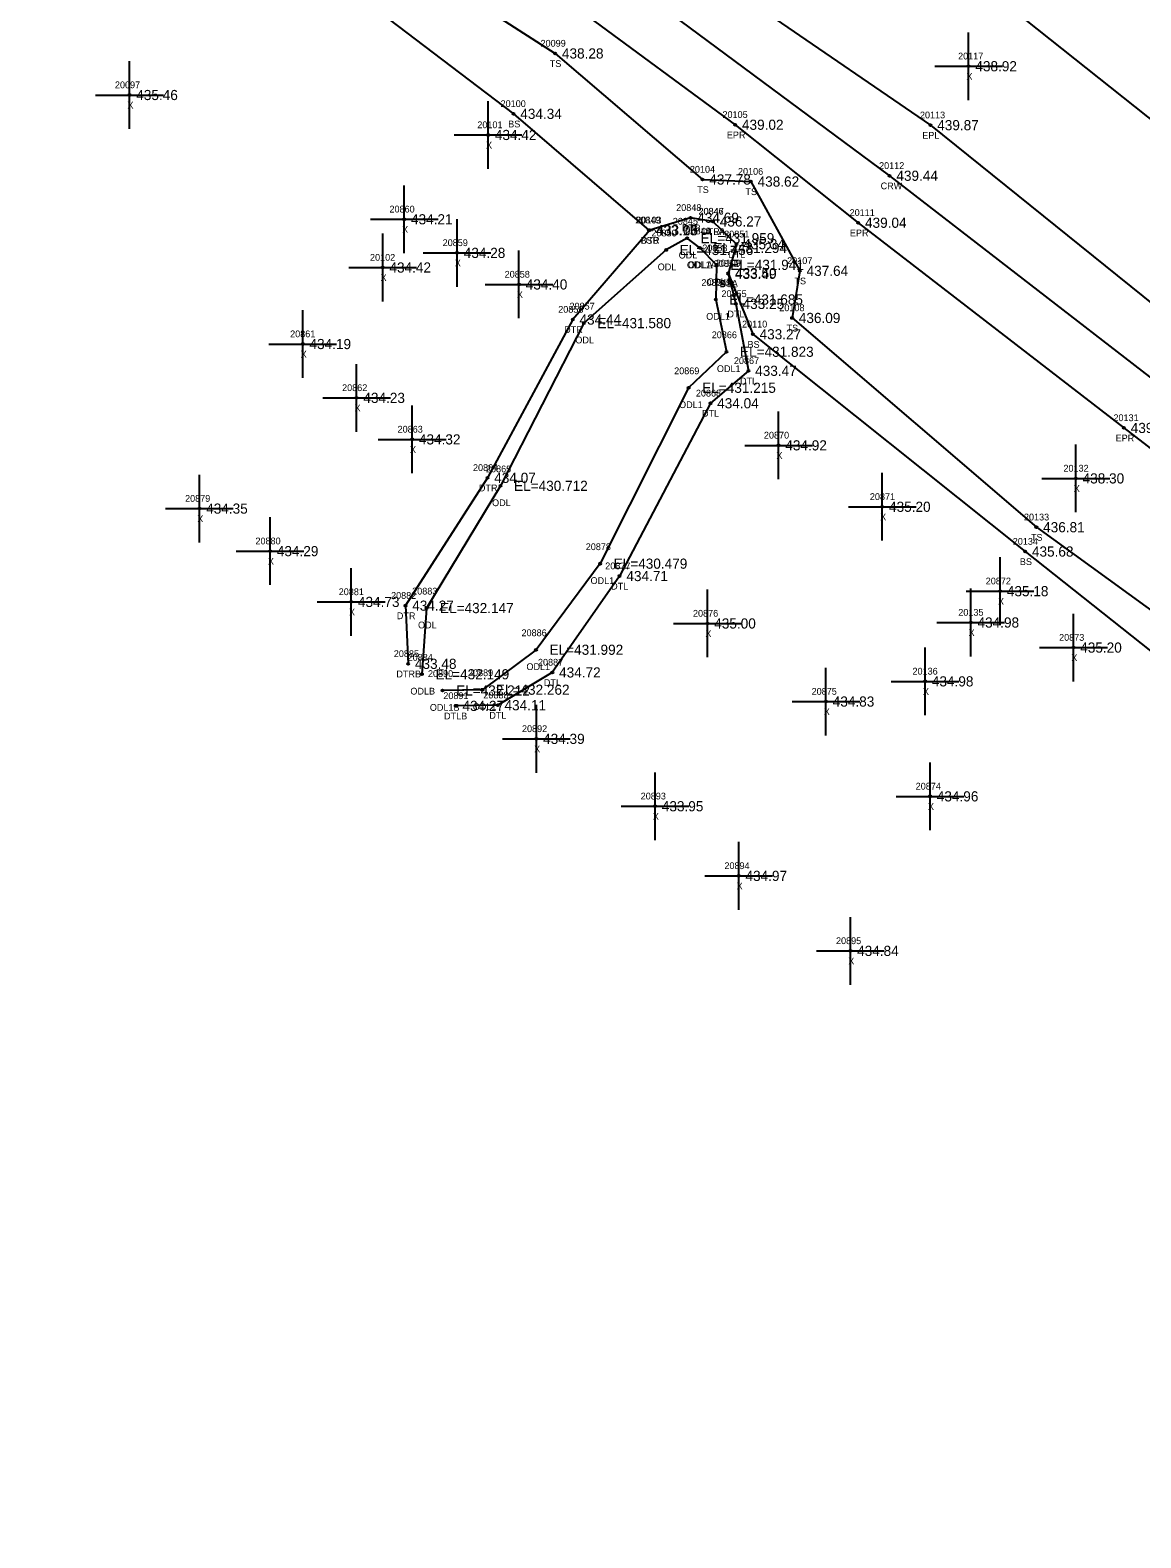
# Model space of a CAD drawing. Extents: x 1613836 to 1615109, y 777151 to 778248.
# Drawn here: x 1614083 to 1614247, y 777695.6 to 777918.3 of the extents above; entities that cross this region are included whole.
import ezdxf

# ---------------------------------------------------------------- set-up
doc = ezdxf.new("R2010")
doc.units = 0
for name, color, linetype in [('RD_DTM_BkLn1', 7, 'Continuous'), ('RD_DTM_BkLn2', 7, 'Continuous'), ('RD_DTM_BkLn_txCode', 7, 'Continuous'), ('RD_EX_H2O', 7, 'Continuous'), ('RD_EX_H2O_txCode', 7, 'Continuous'), ('RD_EX_Misc', 7, 'Continuous'), ('RD_EX_Misc_txCode', 7, 'Continuous'), ('RD_EX_Road', 7, 'Continuous'), ('RD_EX_Road_txCode', 7, 'Continuous'), ('RD_EX_TX_H2O_ELEV', 7, 'Continuous'), ('RD_EX_TX_Misc_ELEV', 7, 'Continuous'), ('RD_EX_TX_Road_ELEV', 7, 'Continuous'), ('RD_HC_Survey_ELEV', 7, 'Continuous'), ('RD_HC_Survey_txCode', 7, 'Continuous'), ('RD_SMD_Locator', 7, 'Continuous')]:
    doc.layers.add(name, color=color, linetype=linetype)

msp = doc.modelspace()

# ---------------------------------------------------------------- linework, layer by layer
at = {"layer": 'RD_DTM_BkLn1'}
msp.add_lwpolyline([(1613865.21, 778095.86), (1613910.73, 778075.92), (1613956.18, 778054.99), (1614000.73, 778032.51), (1614044.52, 778008.68), (1614087.21, 777982.81), (1614129.12, 777955.82), (1614169.63, 777926.64), (1614209.9, 777896.76), (1614249.35, 777866.21), (1614288.43, 777835.55), (1614366.39, 777772.65), (1614443.98, 777709.72)], dxfattribs=at)
at = {"layer": 'RD_DTM_BkLn2'}
for points in [[(1613870.65, 778107.91), (1613917.36, 778089.81), (1613963.47, 778068.53), (1614008.76, 778046.32), (1614052.42, 778023.01), (1614094.96, 777996.37), (1614137.71, 777969), (1614179.06, 777940.06), (1614196.49, 777927.41), (1614202.23, 777922.93), (1614210.94, 777920.91), (1614226.4, 777922.61), (1614267.62, 777889.85), (1614307.16, 777859.76), (1614381.32, 777790.21), (1614451.43, 777721.4), (1614453.49, 777722.08), (1614455.33, 777720.48), (1614437.07, 777696.16)], [(1613860.36, 778083.39), (1613904.96, 778062.9), (1613950.73, 778042.94), (1613994.86, 778021.25), (1614038.25, 777997.65), (1614118.58, 777941.84), (1614160.54, 777914.82), (1614182.29, 777896.21), (1614189.42, 777895.9), (1614196.65, 777882.72), (1614195.5, 777875.76), (1614231.56, 777844.86), (1614271.92, 777815.6), (1614305.89, 777789.49), (1614313.92, 777782.98), (1614351.2, 777751.93), (1614424.47, 777701.24), (1614433.25, 777695.63), (1614437.07, 777696.16)], [(1613858.47, 778079.63), (1613903.77, 778059.57), (1613949.1, 778039.22), (1613993.41, 778017.95), (1614036.6, 777992.42), (1614114.93, 777935.94), (1614154.39, 777905.9), (1614174.38, 777888.71)], [(1614186.09, 777882.37), (1614189.71, 777873.35), (1614229.91, 777841.27), (1614268.42, 777810.69), (1614296.8, 777785.63)]]:
    msp.add_lwpolyline(points, dxfattribs=at)
at = {"layer": 'RD_EX_H2O'}
for points in [[(1614183.83, 777890.01), (1614180.52, 777890.56), (1614174.49, 777888.72), (1614163.13, 777875.53), (1614150.55, 777852.16), (1614138.44, 777833.28), (1614138.84, 777824.69)], [(1614183.83, 777890.01), (1614187.32, 777886.65), (1614186.07, 777882.28), (1614187.2, 777877.84), (1614189.06, 777867.96), (1614183.45, 777863.16), (1614170.05, 777837.65), (1614160.12, 777823.42), (1614152.06, 777818.58), (1614145.86, 777818.48)], [(1614181.88, 777886.1), (1614180.01, 777887.54), (1614176.91, 777885.8), (1614164.77, 777875), (1614152.47, 777850.97), (1614141.54, 777832.92), (1614140.88, 777823.15)], [(1614181.88, 777886.1), (1614184.37, 777883.6), (1614184.24, 777878.49), (1614185.82, 777870.77), (1614180.24, 777865.45), (1614167.17, 777839.48), (1614157.71, 777826.77), (1614149.79, 777820.87), (1614143.92, 777820.75)]]:
    msp.add_lwpolyline(points, dxfattribs=at)
at = {"layer": 'RD_EX_Misc'}
for p, q in [((1614221.56, 777907.93), (1614221.56, 777917.93)), ((1614097.71, 777903.68), (1614097.71, 777913.68)), ((1614216.56, 777912.93), (1614226.56, 777912.93)), ((1614092.71, 777908.68), (1614102.71, 777908.68)), ((1614150.64, 777897.78), (1614150.64, 777907.78)), ((1614145.64, 777902.78), (1614155.64, 777902.78)), ((1614138.26, 777885.33), (1614138.26, 777895.33)), ((1614133.26, 777890.33), (1614143.26, 777890.33)), ((1614146.05, 777880.37), (1614146.05, 777890.37)), ((1614135.08, 777878.21), (1614135.08, 777888.21)), ((1614141.05, 777885.37), (1614151.05, 777885.37)), ((1614155.2, 777875.71), (1614155.2, 777885.71)), ((1614130.08, 777883.21), (1614140.08, 777883.21)), ((1614150.2, 777880.71), (1614160.2, 777880.71)), ((1614123.28, 777866.91), (1614123.28, 777876.91)), ((1614118.28, 777871.91), (1614128.28, 777871.91)), ((1614131.23, 777858.96), (1614131.23, 777868.96)), ((1614126.23, 777863.96), (1614136.23, 777863.96)), ((1614139.43, 777852.83), (1614139.43, 777862.83)), ((1614193.51, 777851.95), (1614193.51, 777861.95)), ((1614134.43, 777857.83), (1614144.43, 777857.83)), ((1614188.51, 777856.95), (1614198.51, 777856.95)), ((1614237.39, 777847.07), (1614237.39, 777857.07)), ((1614108.03, 777842.61), (1614108.03, 777852.61)), ((1614208.82, 777842.88), (1614208.82, 777852.88)), ((1614232.39, 777852.07), (1614242.39, 777852.07)), ((1614103.03, 777847.61), (1614113.03, 777847.61)), ((1614203.82, 777847.88), (1614213.82, 777847.88)), ((1614118.46, 777836.33), (1614118.46, 777846.33)), ((1614113.46, 777841.33), (1614123.46, 777841.33)), ((1614226.21, 777830.42), (1614226.21, 777840.42)), ((1614130.43, 777828.83), (1614130.43, 777838.83)), ((1614125.43, 777833.83), (1614135.43, 777833.83)), ((1614183.02, 777825.65), (1614183.02, 777835.65)), ((1614221.21, 777835.42), (1614231.21, 777835.42)), ((1614221.88, 777825.79), (1614221.88, 777835.79)), ((1614237.04, 777822.09), (1614237.04, 777832.09)), ((1614178.02, 777830.65), (1614188.02, 777830.65)), ((1614216.88, 777830.79), (1614226.88, 777830.79)), ((1614215.14, 777817.1), (1614215.14, 777827.1)), ((1614232.04, 777827.09), (1614242.04, 777827.09)), ((1614200.51, 777814.12), (1614200.51, 777824.12)), ((1614210.14, 777822.1), (1614220.14, 777822.1)), ((1614157.76, 777808.61), (1614157.76, 777818.61)), ((1614195.51, 777819.12), (1614205.51, 777819.12)), ((1614152.76, 777813.61), (1614162.76, 777813.61)), ((1614215.87, 777800.12), (1614215.87, 777810.12)), ((1614175.28, 777798.66), (1614175.28, 777808.66)), ((1614210.87, 777805.12), (1614220.87, 777805.12)), ((1614170.28, 777803.66), (1614180.28, 777803.66)), ((1614187.63, 777788.38), (1614187.63, 777798.38)), ((1614182.63, 777793.38), (1614192.63, 777793.38)), ((1614204.11, 777777.3), (1614204.11, 777787.3)), ((1614199.11, 777782.3), (1614209.11, 777782.3))]:
    msp.add_line(p, q, dxfattribs=at)
at = {"layer": 'RD_EX_Road'}
for points in [[(1613868.87, 778104.15), (1613915.02, 778083.82), (1613960.16, 778062.2), (1614004.58, 778040.28), (1614048.84, 778015.98), (1614091.38, 777990.08), (1614134.36, 777962.6), (1614174.73, 777933.48), (1614192.07, 777920.58), (1614215.93, 777904.23), (1614254.59, 777873.05), (1614293.82, 777842.42), (1614371.74, 777779.59), (1614449.33, 777716.3), (1614443.98, 777709.72), (1614439.38, 777704.09)], [(1613862.14, 778087.92), (1613908.12, 778068.22), (1613952.96, 778047.38), (1613997, 778025.09), (1614041.16, 778001.63), (1614124.35, 777949.06), (1614164.51, 777920.91), (1614187.11, 777904.29), (1614205.27, 777889.82), (1614244.49, 777859.52), (1614283.42, 777829.45), (1614361.06, 777765.89), (1614439.38, 777704.09)]]:
    msp.add_lwpolyline(points, dxfattribs=at)
at = {"layer": 'RD_SMD_Locator'}
for centre in [(1614160.54, 777914.82), (1614221.56, 777912.93), (1614097.71, 777908.68), (1614154.39, 777905.9), (1614150.64, 777902.78), (1614187.11, 777904.29), (1614215.93, 777904.23), (1614182.29, 777896.21), (1614189.42, 777895.9), (1614209.9, 777896.76), (1614138.26, 777890.33), (1614180.52, 777890.56), (1614183.83, 777890.01), (1614183.83, 777890.01), (1614205.27, 777889.82), (1614174.38, 777888.71), (1614174.49, 777888.72), (1614180.01, 777887.54), (1614146.05, 777885.37), (1614176.91, 777885.8), (1614181.88, 777886.1), (1614181.88, 777886.1), (1614187.32, 777886.65), (1614135.08, 777883.21), (1614184.37, 777883.6), (1614196.65, 777882.72), (1614155.2, 777880.71), (1614186.07, 777882.28), (1614186.09, 777882.37), (1614184.24, 777878.49), (1614187.2, 777877.84), (1614163.13, 777875.53), (1614164.77, 777875), (1614195.5, 777875.76), (1614123.28, 777871.91), (1614189.71, 777873.35), (1614185.82, 777870.77), (1614189.06, 777867.96), (1614180.24, 777865.45), (1614131.23, 777863.96), (1614183.45, 777863.16), (1614244.49, 777859.52), (1614139.43, 777857.83), (1614193.51, 777856.95), (1614150.55, 777852.16), (1614237.39, 777852.07), (1614152.47, 777850.97), (1614108.03, 777847.61), (1614208.82, 777847.88), (1614231.56, 777844.86), (1614118.46, 777841.33), (1614229.91, 777841.27), (1614167.17, 777839.48), (1614170.05, 777837.65), (1614130.43, 777833.83), (1614226.21, 777835.42), (1614138.44, 777833.28), (1614141.54, 777832.92), (1614183.02, 777830.65), (1614221.88, 777830.79), (1614237.04, 777827.09), (1614138.84, 777824.69), (1614157.71, 777826.77), (1614140.88, 777823.15), (1614160.12, 777823.42), (1614143.92, 777820.75), (1614149.79, 777820.87), (1614215.14, 777822.1), (1614145.86, 777818.48), (1614152.06, 777818.58), (1614200.51, 777819.12), (1614157.76, 777813.61), (1614215.87, 777805.12), (1614175.28, 777803.66), (1614187.63, 777793.38), (1614204.11, 777782.3)]:
    msp.add_circle(centre, 0.15, dxfattribs=at)

# ---------------------------------------------------------------- texts
at = {"layer": 'RD_DTM_BkLn_txCode'}
for s, p in [('20099', (1614158.38, 777915.82)), ('TS', (1614159.74, 777912.82)), ('20100', (1614152.48, 777906.9)), ('BS', (1614153.61, 777903.9)), ('20104', (1614180.42, 777897.21)), ('20106', (1614187.52, 777896.9)), ('TS', (1614181.5, 777894.21)), ('TS', (1614188.63, 777893.9)), ('20103', (1614172.51, 777889.71)), ('BSB', (1614173.13, 777886.71)), ('20109', (1614184.21, 777883.37)), ('20107', (1614194.78, 777883.72)), ('BSA', (1614184.82, 777880.37)), ('TS', (1614195.86, 777880.72)), ('20108', (1614193.62, 777876.76)), ('20110', (1614188.12, 777874.35)), ('TS', (1614194.7, 777873.76)), ('BS', (1614188.93, 777871.35)), ('20133', (1614229.73, 777845.86)), ('20134', (1614228.08, 777842.27)), ('TS', (1614230.77, 777842.86)), ('BS', (1614229.13, 777839.27))]:
    msp.add_text(s, height=1, dxfattribs=at).set_placement(p)
at = {"layer": 'RD_EX_H2O_txCode'}
for s, p in [('20848', (1614178.4, 777891.56)), ('20846', (1614181.68, 777891.01)), ('20847', (1614181.71, 777891.01)), ('20849', (1614172.37, 777889.72)), ('20845', (1614177.9, 777889.54)), ('DTR', (1614179.25, 777888.56)), ('DTR', (1614173.22, 777886.72)), ('20850', (1614174.75, 777887.8)), ('20843', (1614179.77, 777888.1)), ('20844', (1614179.77, 777888.1)), ('DTRA', (1614182.07, 777888.01)), ('DTLA', (1614182.09, 777888.01)), ('20851', (1614185.48, 777887.65)), ('ODL', (1614178.77, 777884.54)), ('20853', (1614182.25, 777885.6)), ('DTL', (1614186.07, 777884.65)), ('ODL', (1614175.67, 777882.8)), ('ODL1A', (1614179.99, 777883.1)), ('ODLA', (1614180.15, 777883.1)), ('20852', (1614183.95, 777883.28)), ('20854', (1614182.12, 777880.49)), ('ODL1', (1614182.96, 777880.6)), ('DTL', (1614184.83, 777880.28)), ('20855', (1614185.08, 777878.84)), ('20856', (1614160.99, 777876.53)), ('20857', (1614162.65, 777877)), ('ODL1', (1614182.83, 777875.49)), ('DTL', (1614185.96, 777875.84)), ('DTR', (1614161.86, 777873.53)), ('20866', (1614183.65, 777872.77)), ('ODL', (1614163.52, 777872)), ('20867', (1614186.92, 777868.96)), ('20869', (1614178.1, 777867.45)), ('ODL1', (1614184.41, 777867.77)), ('20868', (1614181.31, 777864.16)), ('DTL', (1614187.82, 777865.96)), ('ODL1', (1614178.83, 777862.45)), ('DTL', (1614182.21, 777861.16)), ('20864', (1614148.41, 777853.16)), ('20865', (1614150.33, 777852.97)), ('DTR', (1614149.28, 777850.16)), ('ODL', (1614151.23, 777847.97)), ('20878', (1614165.05, 777841.48)), ('20877', (1614167.93, 777838.65)), ('20883', (1614139.43, 777834.92)), ('ODL1', (1614165.76, 777836.48)), ('DTL', (1614168.8, 777835.65)), ('20882', (1614136.32, 777834.28)), ('DTR', (1614137.17, 777831.28)), ('ODL', (1614140.3, 777829.92)), ('20886', (1614155.57, 777828.77)), ('20885', (1614136.72, 777825.69)), ('20884', (1614138.76, 777825.15)), ('ODL1', (1614156.3, 777823.77)), ('20887', (1614158, 777824.42)), ('DTRB', (1614137.1, 777822.69)), ('20890', (1614141.76, 777822.75)), ('20889', (1614147.67, 777822.87)), ('ODLB', (1614139.17, 777820.15)), ('20891', (1614144.03, 777819.48)), ('20888', (1614149.94, 777819.58)), ('DTL', (1614158.87, 777821.42)), ('ODL1B', (1614142.04, 777817.75)), ('ODL1', (1614148.38, 777817.87)), ('DTLB', (1614144.14, 777816.48)), ('DTL', (1614150.82, 777816.58))]:
    msp.add_text(s, height=1, dxfattribs=at).set_placement(p)
at = {"layer": 'RD_EX_Misc_txCode'}
for s, p in [('20117', (1614220.01, 777913.93)), ('X', (1614221.24, 777910.93)), ('20097', (1614095.56, 777909.68)), ('X', (1614097.4, 777906.68)), ('20101', (1614149.05, 777903.78)), ('X', (1614150.33, 777900.78)), ('20860', (1614136.08, 777891.33)), ('X', (1614137.95, 777888.33)), ('20859', (1614143.93, 777886.37)), ('20102', (1614133.21, 777884.21)), ('X', (1614145.73, 777883.37)), ('20858', (1614153.08, 777881.71)), ('X', (1614134.77, 777881.21)), ('X', (1614154.89, 777878.71)), ('20861', (1614121.42, 777872.91)), ('X', (1614122.97, 777869.91)), ('20862', (1614129.09, 777864.96)), ('X', (1614130.92, 777861.96)), ('20863', (1614137.28, 777858.83)), ('20870', (1614191.35, 777857.95)), ('X', (1614139.11, 777855.83)), ('X', (1614193.19, 777854.95)), ('20132', (1614235.56, 777853.07)), ('20879', (1614105.91, 777848.61)), ('20871', (1614206.99, 777848.88)), ('X', (1614237.08, 777850.07)), ('X', (1614107.71, 777845.61)), ('X', (1614208.51, 777845.88)), ('20880', (1614116.3, 777842.33)), ('X', (1614118.14, 777839.33)), ('20872', (1614224.09, 777836.42)), ('20881', (1614128.59, 777834.83)), ('X', (1614225.9, 777833.42)), ('X', (1614130.11, 777831.83)), ('20876', (1614180.88, 777831.65)), ('20135', (1614220.04, 777831.79)), ('X', (1614182.71, 777828.65)), ('X', (1614221.56, 777828.79)), ('20873', (1614234.92, 777828.09)), ('X', (1614236.72, 777825.09)), ('20136', (1614213.28, 777823.1)), ('20875', (1614198.39, 777820.12)), ('X', (1614214.82, 777820.1)), ('X', (1614200.19, 777817.12)), ('20892', (1614155.64, 777814.61)), ('X', (1614157.44, 777811.61)), ('20874', (1614213.75, 777806.12)), ('20893', (1614173.16, 777804.66)), ('X', (1614174.96, 777801.66)), ('X', (1614215.56, 777803.12)), ('20894', (1614185.52, 777794.38)), ('X', (1614187.32, 777791.38)), ('20895', (1614201.99, 777783.3)), ('X', (1614203.8, 777780.3))]:
    msp.add_text(s, height=1, dxfattribs=at).set_placement(p)
at = {"layer": 'RD_EX_Road_txCode'}
for s, p in [('20105', (1614185.23, 777905.29)), ('20113', (1614214.38, 777905.23)), ('EPR', (1614185.88, 777902.29)), ('EPL', (1614214.72, 777902.23)), ('20111', (1614204, 777890.82)), ('EPR', (1614204.04, 777887.82)), ('20131', (1614242.94, 777860.52)), ('EPR', (1614243.26, 777857.52))]:
    msp.add_text(s, height=1, dxfattribs=at).set_placement(p)
at = {"layer": 'RD_EX_TX_H2O_ELEV'}
for s, p in [('433.06', (1614175.49, 777887.97)), ('434.69', (1614181.52, 777889.81)), ('436.27', (1614184.83, 777889.26)), ('436.27', (1614184.83, 777889.26)), ('EL=431.959', (1614182.01, 777886.79)), ('435.34', (1614188.32, 777885.9)), ('EL=431.456', (1614178.91, 777885.05)), ('EL=431.294', (1614183.88, 777885.35)), ('EL=431.294', (1614183.88, 777885.35)), ('EL=431.941', (1614186.37, 777882.85)), ('433.49', (1614187.07, 777881.53)), ('EL=431.685', (1614186.24, 777877.74)), ('433.25', (1614188.2, 777877.09)), ('434.44', (1614164.13, 777874.78)), ('EL=431.580', (1614166.77, 777874.25)), ('EL=431.823', (1614187.82, 777870.02)), ('433.47', (1614190.06, 777867.21)), ('EL=431.215', (1614182.24, 777864.7)), ('434.04', (1614184.45, 777862.41)), ('434.07', (1614151.55, 777851.41)), ('EL=430.712', (1614154.47, 777850.22)), ('EL=430.479', (1614169.17, 777838.73)), ('434.71', (1614171.05, 777836.9)), ('434.27', (1614139.44, 777832.53)), ('EL=432.147', (1614143.54, 777832.17)), ('EL=431.992', (1614159.71, 777826.02)), ('433.48', (1614139.84, 777823.94)), ('EL=432.149', (1614142.88, 777822.4)), ('434.72', (1614161.12, 777822.67)), ('EL=432.212', (1614145.92, 777820)), ('EL=432.262', (1614151.79, 777820.12)), ('434.27', (1614146.86, 777817.73)), ('434.11', (1614153.06, 777817.83))]:
    msp.add_text(s, height=1.5, dxfattribs=at).set_placement(p)
at = {"layer": 'RD_EX_TX_Misc_ELEV'}
for s, p in [('438.28', (1614161.54, 777914.07)), ('438.92', (1614222.56, 777912.18)), ('435.46', (1614098.71, 777907.93)), ('434.34', (1614155.39, 777905.15)), ('434.42', (1614151.64, 777902.03)), ('437.78', (1614183.29, 777895.46)), ('438.62', (1614190.42, 777895.15)), ('434.21', (1614139.26, 777889.58)), ('433.13', (1614175.38, 777887.96)), ('434.28', (1614147.05, 777884.62)), ('434.42', (1614136.08, 777882.46)), ('433.50', (1614187.09, 777881.62)), ('437.64', (1614197.65, 777881.97)), ('434.40', (1614156.2, 777879.96)), ('436.09', (1614196.5, 777875.01)), ('433.27', (1614190.71, 777872.6)), ('434.19', (1614124.28, 777871.16)), ('434.23', (1614132.23, 777863.21)), ('434.32', (1614140.43, 777857.08)), ('434.92', (1614194.51, 777856.2)), ('438.30', (1614238.39, 777851.32)), ('434.35', (1614109.03, 777846.86)), ('435.20', (1614209.82, 777847.13)), ('436.81', (1614232.56, 777844.11)), ('434.29', (1614119.46, 777840.58)), ('435.68', (1614230.91, 777840.52)), ('435.18', (1614227.21, 777834.67)), ('434.73', (1614131.43, 777833.08)), ('435.00', (1614184.02, 777829.9)), ('434.98', (1614222.88, 777830.04)), ('435.20', (1614238.04, 777826.34)), ('434.98', (1614216.14, 777821.35)), ('434.83', (1614201.51, 777818.37)), ('434.39', (1614158.76, 777812.86)), ('434.96', (1614216.87, 777804.37)), ('433.95', (1614176.28, 777802.91)), ('434.97', (1614188.63, 777792.63)), ('434.84', (1614205.11, 777781.55))]:
    msp.add_text(s, height=1.5, dxfattribs=at).set_placement(p)
at = {"layer": 'RD_EX_TX_Road_ELEV'}
for s, p in [('439.02', (1614188.11, 777903.54)), ('439.87', (1614216.93, 777903.48)), ('439.04', (1614206.27, 777889.07)), ('439.39', (1614245.49, 777858.77))]:
    msp.add_text(s, height=1.5, dxfattribs=at).set_placement(p)
at = {"layer": 'RD_HC_Survey_ELEV'}
msp.add_text('439.44', height=1.5, dxfattribs=at).set_placement((1614210.9, 777896.01))
at = {"layer": 'RD_HC_Survey_txCode'}
for s, p in [('20112', (1614208.35, 777897.76)), ('CRW', (1614208.58, 777894.76))]:
    msp.add_text(s, height=1, dxfattribs=at).set_placement(p)

doc.saveas('drawing.dxf')
